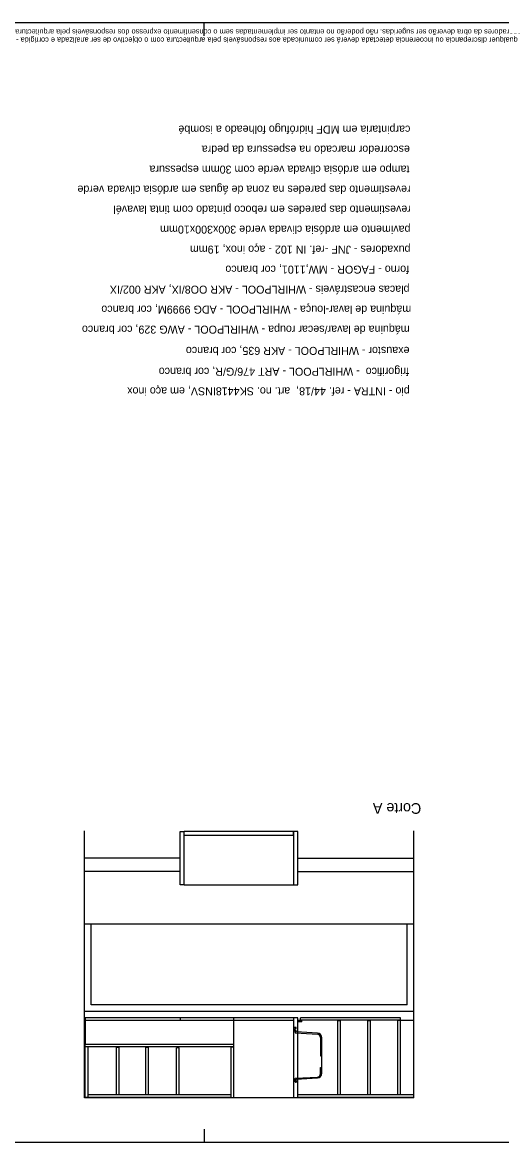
# Model space of a CAD drawing. Extents: x 1306.3 to 1323.2, y -308.3 to -299.9.
# Drawn here: x 1313.92 to 1317.51, y -308.35 to -299.95 of the extents above; entities that cross this region are included whole.
import ezdxf

# ---------------------------------------------------------------- set-up
doc = ezdxf.new("R2010")
doc.units = 0
for name, color, linetype in [('Level 1', 7, 'Continuous'), ('Level 11', 7, 'Continuous'), ('Level 13', 7, 'Continuous'), ('Level 14', 7, 'Continuous'), ('Level 2', 7, 'Continuous'), ('Level 60', 7, 'Continuous'), ('Level 62', 7, 'Continuous')]:
    doc.layers.add(name, color=color, linetype=linetype)

msp = doc.modelspace()

# ---------------------------------------------------------------- linework, layer by layer
at = {"layer": 'Level 1'}
for p, q in [((1314.3809, -308.0087), (1314.3809, -306.0087)), ((1316.8509, -308.0087), (1316.8509, -306.0087)), ((1315.0969, -306.4137), (1315.0969, -306.0137)), ((1315.0969, -306.0137), (1315.1269, -306.0137)), ((1315.1269, -306.4137), (1315.1269, -306.0137)), ((1315.9809, -306.0137), (1315.9509, -306.0137)), ((1315.9509, -306.4137), (1315.9509, -306.0137)), ((1315.9809, -306.4137), (1315.9809, -306.0137)), ((1315.0969, -306.2137), (1314.3809, -306.2137)), ((1315.9809, -306.2137), (1316.8509, -306.2137)), ((1315.0969, -306.3137), (1314.3809, -306.3137)), ((1315.9809, -306.3137), (1316.8509, -306.3137)), ((1315.1269, -306.4137), (1315.0969, -306.4137)), ((1315.9509, -306.4137), (1315.9809, -306.4137)), ((1315.9509, -308.0087), (1315.9509, -307.4087)), ((1315.9809, -307.4087), (1315.9509, -307.4087)), ((1315.9809, -308.0087), (1315.9809, -307.4087)), ((1316.0109, -307.4287), (1315.9809, -307.4287)), ((1316.0109, -307.4387), (1315.9809, -307.4387)), ((1316.0009, -307.4277), (1316.0009, -307.4087)), ((1316.7509, -307.4087), (1316.0009, -307.4087)), ((1316.7509, -307.4277), (1316.0009, -307.4277)), ((1316.0109, -307.4387), (1316.0109, -307.4287)), ((1316.2809, -307.9867), (1316.2809, -307.4327)), ((1316.3009, -307.4327), (1316.2809, -307.4327)), ((1316.3009, -307.9867), (1316.3009, -307.4327)), ((1316.5059, -307.9867), (1316.5059, -307.4327)), ((1316.5259, -307.4327), (1316.5059, -307.4327)), ((1316.5259, -307.9867), (1316.5259, -307.4327)), ((1316.8509, -307.4287), (1316.7309, -307.4287)), ((1316.7309, -307.9867), (1316.7309, -307.4287)), ((1316.7509, -307.4277), (1316.7509, -307.4087)), ((1316.7509, -307.9867), (1316.7509, -307.4287)), ((1316.8509, -307.4307), (1316.7509, -307.4307)), ((1315.5009, -307.6087), (1314.3859, -307.6087)), ((1314.3859, -307.9867), (1314.3859, -307.6087)), ((1315.5009, -307.6277), (1314.3859, -307.6277)), ((1314.4059, -307.6277), (1314.4059, -308.0067)), ((1314.6176, -307.6327), (1314.6176, -307.9867)), ((1314.6376, -307.6327), (1314.6176, -307.6327)), ((1314.6376, -307.6327), (1314.6376, -307.9867)), ((1314.8392, -307.6327), (1314.8392, -307.9867)), ((1314.8592, -307.6327), (1314.8392, -307.6327)), ((1314.8592, -307.6327), (1314.8592, -307.9867)), ((1315.0709, -307.9867), (1315.0709, -307.6337)), ((1315.0909, -307.6337), (1315.0709, -307.6337)), ((1315.0909, -307.9867), (1315.0909, -307.6337)), ((1315.4809, -308.0087), (1315.4809, -307.6287)), ((1315.5009, -307.6287), (1315.4809, -307.6287)), ((1315.5009, -307.6277), (1315.5009, -307.6087)), ((1315.5009, -308.0087), (1315.5009, -307.6287)), ((1316.8509, -308.0087), (1314.3809, -308.0087)), ((1314.3859, -308.0087), (1314.3859, -307.9867)), ((1315.4809, -308.0067), (1314.3859, -308.0067)), ((1315.4809, -307.9867), (1314.4059, -307.9867)), ((1316.8509, -307.9867), (1315.9809, -307.9867)), ((1316.8509, -308.0067), (1315.9809, -308.0067))]:
    msp.add_line(p, q, dxfattribs=at)
at = {"layer": 'Level 11'}
for p, q in [((1315.9535, -307.5077), (1315.9575, -307.5077)), ((1315.9605, -307.5107), (1315.9605, -307.5197)), ((1315.9635, -307.5227), (1316.1268, -307.5314)), ((1316.1605, -307.826), (1316.1605, -307.5594)), ((1315.9633, -307.8627), (1316.1268, -307.854)), ((1315.9605, -307.8895), (1315.9605, -307.8657)), ((1315.9809, -307.8934), (1315.9633, -307.8925))]:
    msp.add_line(p, q, dxfattribs=at)
for points in [[(1315.9575, -307.5007), (1315.9575, -307.4897), (1315.9675, -307.4897), (1315.9675, -307.4827), (1315.9535, -307.4827)], [(1316.1274, -307.5245), (1315.9675, -307.5159), (1315.9675, -307.5107)], [(1316.1505, -307.5564), (1316.1505, -307.6937), (1316.1605, -307.6937)], [(1316.1505, -307.829), (1316.1505, -307.7817), (1316.1605, -307.7817)], [(1315.9809, -307.8864), (1315.9675, -307.8857), (1315.9675, -307.8695), (1316.1274, -307.8609)]]:
    msp.add_lwpolyline(points, dxfattribs=at)
for centre, radius, start, end in [((1315.9535, -307.4857), 0.003, 89.99996, 180.00004), ((1315.9535, -307.5047), 0.003, 179.99996, 270.00004), ((1315.9575, -307.5107), 0.01, 359.99996, 90.00004), ((1315.9575, -307.5107), 0.003, 359.99996, 90.00004), ((1315.9635, -307.5197), 0.003, 179.99996, 270.00004), ((1316.1255, -307.5564), 0.025, 359.99921, 86.9382), ((1316.1255, -307.5594), 0.035, 0.00003, 86.93902), ((1316.1255, -307.829), 0.025, 273.0618, 0.00079), ((1316.1255, -307.826), 0.035, 273.06098, 359.99997), ((1315.9635, -307.8657), 0.003, 93.05214, 179.99113), ((1315.9635, -307.8895), 0.003, 179.99932, 266.93831)]:
    msp.add_arc(centre, radius, start, end, dxfattribs=at)
at = {"layer": 'Level 13'}
for p, q in [((1315.9509, -306.0137), (1315.1269, -306.0137)), ((1315.9489, -306.0437), (1315.1289, -306.0437)), ((1315.1269, -306.4137), (1315.9509, -306.4137)), ((1314.3859, -307.4087), (1314.3859, -307.6087)), ((1315.9509, -307.4087), (1314.3859, -307.4087)), ((1315.9509, -307.4287), (1314.3859, -307.4287)), ((1315.1009, -307.4287), (1315.1009, -307.4087)), ((1315.5009, -307.6087), (1315.5009, -307.4087))]:
    msp.add_line(p, q, dxfattribs=at)
at = {"layer": 'Level 14'}
for p, q in [((1315.1289, -306.0437), (1315.1289, -306.0137)), ((1315.9489, -306.0437), (1315.9489, -306.0137))]:
    msp.add_line(p, q, dxfattribs=at)
at = {"layer": 'Level 2'}
for p, q in [((1316.8509, -306.7087), (1314.3859, -306.7087)), ((1314.4309, -307.3112), (1314.4309, -306.7087)), ((1316.8009, -307.3112), (1316.8009, -306.7087)), ((1316.8009, -307.3112), (1314.4309, -307.3112)), ((1316.8509, -307.3612), (1314.3809, -307.3612))]:
    msp.add_line(p, q, dxfattribs=at)
at = {"layer": 'Level 62'}
for p, q in [((1315.2776, -300.0454), (1315.2776, -299.9454)), ((1315.2776, -308.2454), (1315.2776, -308.3454))]:
    msp.add_line(p, q, dxfattribs=at)
msp.add_lwpolyline([(1323.1772, -299.9454), (1323.1772, -308.3454), (1311.5776, -308.3454), (1311.5776, -299.9454)], close=True, dxfattribs=at)

# ---------------------------------------------------------------- texts
at = {"layer": 'Level 60'}
for s, height, p in [('carpintaria em MDF hidrófugo folheado a isombé', 0.06, (1316.8238, -300.7192)), ('escorredor marcado na espessura da pedra', 0.06, (1316.8206, -300.8692)), ('tampo em ardósia clivada verde com 30mm espessura', 0.06, (1316.8167, -301.0192)), ('revestimento das paredes na zona de águas em ardósia clivada verde', 0.06, (1316.8255, -301.1692)), ('revestimento das paredes em reboco pintado com tinta lavavél ', 0.06, (1316.8277, -301.3192)), ('pavimento em ardósia clivada verde 300x300x10mm', 0.06, (1316.825, -301.4692)), ('puxadores - JNF -ref. IN 102 - aço inox, 19mm ', 0.06, (1316.8251, -301.6192)), ('forno - FAGOR - MW,1101, cor branco', 0.06, (1316.8147, -301.7692)), ('placas encastráveis - WHIRLPOOL - AKR OO8/IX, AKR 002/IX', 0.06, (1316.8177, -301.9192)), ('máquina de lavar-louça - WHIRLPOOL - ADG 9999M, cor branco', 0.06, (1316.8303, -302.0692)), ('máquina de lavar/secar roupa - WHIRLPOOL - AWG 329, cor branco', 0.06, (1316.8186, -302.2192)), ('exaustor - WHIRLPOOL - AKR 635, cor branco', 0.06, (1316.8174, -302.3785)), ('frigorifico  - WHIRLPOOL - ART 476/G/R, cor branco', 0.06, (1316.8145, -302.5349)), ('pio - INTRA - ref. 44/18,  art. no. SK4418INSV, em aço inox', 0.06, (1316.8192, -302.6818)), ('Corte A', 0.08, (1316.9056, -305.7999))]:
    msp.add_text(s, height=height, rotation=180.00001, dxfattribs=at).set_placement(p)
at = {"layer": 'Level 62'}
for s, p in [('qualquer discrepancia ou incoerencia detectada deverá ser comunicada aos responsáveis pela arquitectura com o objectivo de ser analizada e corrigida -', (1317.6289, -300.0584)), ('cutantes e preparadores da obra deverão ser sugeridas. não poderão no entanto ser implementadas sem o consentimento expresso dos responsáveis pela arquitectura', (1317.9755, -299.9974))]:
    msp.add_text(s, height=0.0399996, rotation=180, dxfattribs=at).set_placement(p)

doc.saveas('drawing.dxf')
